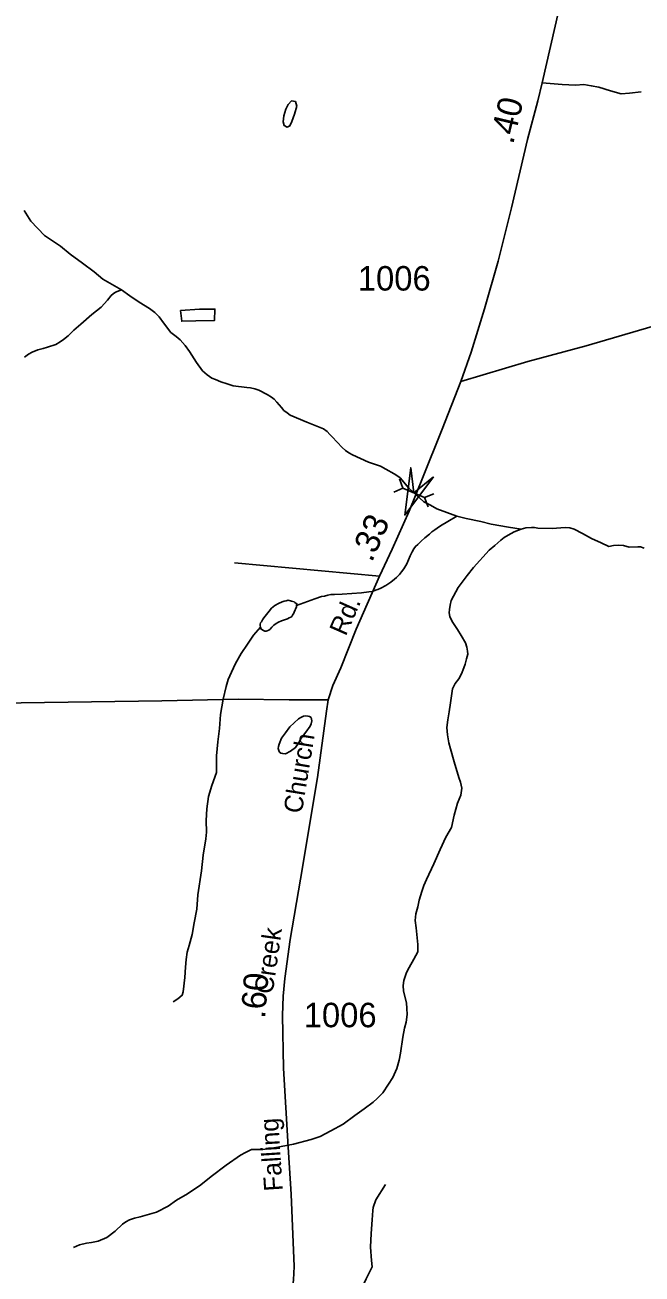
# Model space of a CAD drawing. Extents: x 2206922 to 2357709, y 510027 to 673830.
# Drawn here: x 2248244 to 2251391, y 564362 to 570736 of the extents above; entities that cross this region are included whole.
import ezdxf

# ---------------------------------------------------------------- set-up
doc = ezdxf.new("R2010")
doc.units = 0
for name, color, linetype in [('Exist Hydrographic Creek Single Shore', 7, 'Continuous'), ('Exist Hydrographic Misc Water Feature', 7, 'Continuous'), ('Exist Road Non-System Type 51', 7, 'Continuous'), ('Exist Road Secondary Mileage Hundredths English Label', 7, 'Continuous'), ('Exist Road Secondary Structure Pipe Attributed CELL', 7, 'Continuous'), ('Exist Road Secondary Structure Pipe CELL', 7, 'Continuous'), ('Exist Road Secondary Type 51 Attributed', 7, 'Continuous'), ('Exist Road Secondary Type 51 Label', 7, 'Continuous'), ('Exist Road Secondary Type 51 Number Label', 7, 'Continuous')]:
    doc.layers.add(name, color=color, linetype=linetype)

msp = doc.modelspace()

# ---------------------------------------------------------------- linework, layer by layer
at = {"layer": 'Exist Hydrographic Creek Single Shore'}
for points in [[(2248239, 569789.7), (2248273.1, 569734.3), (2248343.8, 569660.8), (2248424.6, 569607.3), (2248474.6, 569565.6), (2248536.8, 569520.2), (2248597, 569477), (2248641.3, 569439.1), (2248735.9, 569383.9)], [(2248240.9, 569040), (2248261, 569056.1), (2248280.4, 569066.5), (2248308.5, 569078.5), (2248336.6, 569084.8), (2248358.6, 569091.2), (2248400.6, 569105.6), (2248424, 569119.5), (2248440.2, 569131.6), (2248463.6, 569150), (2248493.7, 569178.3), (2248529.4, 569208.6), (2248584.9, 569259), (2248632.7, 569295.2), (2248664.3, 569331.5), (2248684, 569355.6), (2248693.8, 569363.9), (2248706.1, 569371.8), (2248735.9, 569383.9)], [(2248735.9, 569383.9), (2248778.1, 569354.4), (2248826.1, 569320.8), (2248878.6, 569289.4), (2248906.9, 569269.3), (2248928.8, 569245.7), (2248951, 569216), (2248987.9, 569166.2), (2249015.6, 569146.3), (2249035.9, 569128.6), (2249060.3, 569100.6), (2249082.6, 569068.8), (2249118.7, 569013.5), (2249149.3, 568971.6), (2249173.2, 568949.8), (2249197.4, 568933.9), (2249215.3, 568926.4), (2249243.4, 568914.4), (2249275.4, 568904.8), (2249305.7, 568894.9), (2249375.4, 568885.6), (2249393.9, 568883.6), (2249415.8, 568879.9), (2249437.3, 568872.2), (2249479.8, 568850.4), (2249501.9, 568836.5), (2249514, 568826.6), (2249528.4, 568810.6), (2249552.2, 568783.1), (2249564.7, 568769.1), (2249580.7, 568757.3), (2249596.5, 568745.2), (2249681, 568708.2), (2249748.8, 568682.5), (2249767.1, 568674.9), (2249785.1, 568660.8), (2249799.5, 568646.9), (2249811.2, 568633.4), (2249861.8, 568579.5), (2249878.2, 568563.6), (2249895.8, 568552.1), (2249914.1, 568542), (2249996.3, 568504.9), (2250056.4, 568485.3), (2250084.9, 568469.6), (2250126.9, 568445.8), (2250144.8, 568433.8), (2250157.3, 568424.2), (2250201.4, 568372.6), (2250277.9, 568303.1), (2250312.3, 568285.3), (2250344.1, 568267.5), (2250446.4, 568228.5)], [(2250446.4, 568228.5), (2250494.6, 568216.9), (2250568.6, 568201.6), (2250622.3, 568187.8), (2250710.9, 568172.9), (2250774.7, 568163.2)], [(2250774.7, 568163.2), (2250798.7, 568169.4), (2250826.8, 568171.6), (2250842.4, 568171.7), (2250860.4, 568167.7), (2250932.6, 568166.6), (2250998.8, 568170.8), (2251022.6, 568169.2), (2251044.8, 568163.5), (2251087, 568141.7), (2251133.3, 568116.1), (2251183.4, 568092.7), (2251221.1, 568074.9), (2251245.3, 568078.9), (2251271.1, 568081.5), (2251297.2, 568079.6), (2251325.7, 568071.7), (2251369.1, 568072), (2251383.1, 568072.3), (2251401.3, 568066.3)]]:
    msp.add_lwpolyline(points, dxfattribs=at)
at = {"layer": 'Exist Hydrographic Misc Water Feature'}
for points in [[(2249603.9, 570348.7), (2249623.5, 570344.6), (2249629.7, 570320.9), (2249618.4, 570280.9), (2249604.5, 570242.8), (2249594.8, 570220.7), (2249580.5, 570214.4), (2249566.5, 570222.2), (2249560.6, 570242.2), (2249564.3, 570272.4), (2249573.7, 570306.2), (2249585.8, 570330.4), (2249603.9, 570348.7)], [(2249036.7, 569278.5), (2249134.7, 569285.2), (2249212.6, 569286), (2249210.6, 569228), (2249115.4, 569225.3), (2249043, 569224.4), (2249036.7, 569278.5)], [(2249628.7, 567774), (2249722.6, 567806.9), (2249756.4, 567819.2), (2249772, 567821.3), (2249788, 567825.4), (2249804, 567829.5), (2249821.8, 567829.6), (2249861.8, 567832.1), (2249959.8, 567838.8), (2249998, 567843.2), (2250015.8, 567845.4), (2250031.8, 567851.5), (2250043.9, 567855.3), (2250059.7, 567861.5), (2250083.7, 567875.7), (2250109.5, 567892.1), (2250129.2, 567908.2), (2250139, 567916), (2250154.8, 567932.3), (2250164.9, 567944.5), (2250177, 567960.6), (2250190.7, 567986.5), (2250207.9, 568026.9), (2250218.2, 568046.9), (2250228, 568062.8), (2250236, 568075), (2250247.9, 568085), (2250265.3, 568100.9), (2250283.4, 568119.4), (2250307.6, 568137.6), (2250318.9, 568149.6), (2250335.1, 568159.8), (2250347, 568167.7), (2250363.2, 568179.9), (2250400.9, 568202.2), (2250446.4, 568228.5)], [(2250417.7, 567798.5), (2250453.4, 567865), (2250499.1, 567927), (2250530.9, 567967.3), (2250611.9, 568056), (2250639.8, 568080.2), (2250671.4, 568106.2), (2250687.3, 568120.5), (2250708.9, 568132.6), (2250738.8, 568148.8), (2250774.7, 568163.2)], [(2248491.6, 564496.5), (2248521.6, 564510.6), (2248557.9, 564518.9), (2248583.7, 564523.2), (2248617.3, 564529.5), (2248661.2, 564548), (2248703.3, 564580.2), (2248740.8, 564616.3), (2248758.4, 564628.6), (2248776.7, 564638.9), (2248802.3, 564647.2), (2248830.6, 564653), (2248914.1, 564677.7), (2248974.1, 564708.4), (2249015.8, 564738.7), (2249073.4, 564770.9), (2249141, 564817.5), (2249192.7, 564859.9), (2249270.2, 564916.8), (2249343.4, 564969), (2249369.3, 564981.3), (2249399.2, 564997.5), (2249457.6, 564998), (2249515.1, 565006.4), (2249613.1, 565025.3), (2249703.1, 565048.2), (2249748.6, 565064.4), (2249804.4, 565092.9), (2249866.3, 565127.4), (2249925.6, 565170), (2249973.4, 565204.1), (2250019.1, 565238.6), (2250040.8, 565256.8), (2250068.9, 565287.1), (2250098.2, 565331.3), (2250120.2, 565365.3), (2250139.7, 565411.4), (2250153.2, 565453.6), (2250159.1, 565489.6), (2250170.4, 565569.8), (2250179.6, 565615.9), (2250187.6, 565647.6), (2250193.4, 565685.6), (2250191.1, 565717.5), (2250189.1, 565745.8), (2250174.3, 565805.6), (2250172.3, 565833.5), (2250175.9, 565859.3), (2250189.7, 565899.9), (2250203.2, 565925.8), (2250226.8, 565968), (2250246.9, 566006), (2250248.3, 566043.9), (2250244.2, 566077.8), (2250239.9, 566127.9), (2250233.4, 566165.8), (2250237.1, 566199.7), (2250246.9, 566235.9), (2250254.7, 566270), (2250268.4, 566314.2), (2250278.1, 566344), (2250291.6, 566374.4), (2250329.1, 566454.3), (2250362.3, 566528.7), (2250389.6, 566591.1), (2250419.3, 566641), (2250433.1, 566703), (2250450.1, 566765.3), (2250466.1, 566805.4), (2250471.8, 566841.5), (2250465.7, 566871.2), (2250457.3, 566895.2), (2250432.9, 566975.1), (2250414.4, 567042.8), (2250405.8, 567072.9), (2250399.7, 567112.8), (2250395.4, 567150.7), (2250400.7, 567190.8), (2250406.6, 567230.9), (2250414.2, 567276.8), (2250423.6, 567348.8), (2250437.4, 567375.1), (2250457.1, 567398.9), (2250470.8, 567425.2), (2250482.7, 567455.4), (2250488.7, 567473.2), (2250496.6, 567501.2), (2250502.4, 567525.5), (2250500.3, 567541.2), (2250497.7, 567561.5), (2250489.9, 567583.3), (2250469.4, 567620.9), (2250449.3, 567650.7), (2250426.7, 567686.5), (2250417.1, 567702.6), (2250410.9, 567716.5), (2250406.6, 567736.6), (2250408.5, 567752.5), (2250412, 567774.3), (2250417.7, 567798.5)], [(2249445.6, 567662.5), (2249443.5, 567670.5), (2249443.1, 567678.7), (2249445.3, 567684.4), (2249449.4, 567690.7), (2249455.4, 567700.8), (2249461.3, 567710.8), (2249488.6, 567744.8), (2249500.7, 567759.2), (2249518.3, 567773.2), (2249536.6, 567783.4), (2249556.3, 567791.4), (2249566.3, 567795.6), (2249576.4, 567797.7), (2249586.6, 567799.8), (2249602.4, 567795.8), (2249616.4, 567792.1), (2249620.3, 567788.2), (2249626.4, 567784), (2249630.9, 567782.2), (2249628.7, 567774)], [(2249628.7, 567774), (2249628.7, 567766.3), (2249617, 567740.1), (2249614.7, 567733.9), (2249608.8, 567723.9), (2249605.3, 567717.9), (2249599.1, 567714), (2249591.1, 567709.9), (2249583.3, 567705.8), (2249551.4, 567695.6), (2249537.2, 567687.6), (2249525.1, 567681.3), (2249513.2, 567673.4), (2249503.4, 567663.1), (2249493.7, 567652.8), (2249487.6, 567646.9), (2249479.6, 567644.8), (2249473.6, 567642.9), (2249467.9, 567642.9), (2249459.7, 567645), (2249451.7, 567650.7), (2249447.8, 567652.4), (2249445.6, 567662.5)], [(2248999.2, 565750.1), (2249023.6, 565766.3), (2249045.3, 565784.5), (2249050.8, 565802.3), (2249058.6, 565874.5), (2249062.1, 565928.4), (2249065.4, 565966.4), (2249071.3, 566004.4), (2249081.2, 566038.6), (2249096.6, 566094.7), (2249106, 566154.5), (2249119.5, 566224.6), (2249125.1, 566296.8), (2249144.1, 566418.8), (2249153.1, 566499), (2249166.7, 566582.9), (2249170.4, 566616.8), (2249167.9, 566676.8), (2249171.2, 566735.1), (2249180.6, 566799), (2249196.4, 566855), (2249219.8, 566921.2), (2249221.2, 567006.9), (2249228.2, 567077.3), (2249235.8, 567145.1), (2249241.3, 567217.2), (2249254.6, 567295.1), (2249270, 567359.3), (2249279.9, 567395.5), (2249297.7, 567433.8), (2249317, 567477.9), (2249346.7, 567527.8), (2249378.5, 567576.1), (2249410.1, 567622.5), (2249445.6, 567662.5)], [(2249534.5, 567043.6), (2249536.2, 567053.5), (2249540.5, 567065.9), (2249552.2, 567095.7), (2249571.9, 567124), (2249595.4, 567154.1), (2249639.3, 567194.5), (2249651.2, 567202.5), (2249665, 567208.5), (2249675, 567210.6), (2249687.1, 567208.8), (2249695.3, 567206.8), (2249703.3, 567201.1), (2249705.4, 567193.1), (2249707.4, 567185.1), (2249703.5, 567169), (2249697.6, 567156.9), (2249676, 567127), (2249651.8, 567096.6), (2249638.1, 567070.6), (2249624.2, 567048.4), (2249598.7, 567030.3), (2249572.9, 567016), (2249558.9, 567018.1), (2249548.9, 567020), (2249542.7, 567025.8), (2249538.4, 567033.7), (2249534.5, 567043.6)]]:
    msp.add_lwpolyline(points, dxfattribs=at)
at = {"layer": 'Exist Road Non-System Type 51'}
msp.add_line((2249311.8, 567991.6), (2250052.2, 567922.8), dxfattribs=at)
for points in [[(2250882.3, 570441.3), (2250983.5, 570431.8), (2251052.3, 570428), (2251094.4, 570431.8), (2251132.6, 570426), (2251170.8, 570418.4), (2251230, 570399.3), (2251285.4, 570384), (2251327.5, 570387.8), (2251386.7, 570395.5)], [(2249892.5, 564126), (2249937.6, 564242.2), (2249984.7, 564336.6), (2250004.4, 564378.8), (2250014.4, 564398.8), (2250012, 564430.8), (2250005.4, 564498.8), (2250009, 564568.7), (2250014.4, 564638.7), (2250018, 564686.6), (2250019.9, 564700.6), (2250033.5, 564740.7), (2250082.9, 564819.1)]]:
    msp.add_lwpolyline(points, dxfattribs=at)
at = {"layer": 'Exist Road Secondary Structure Pipe Attributed CELL'}
msp.add_lwpolyline([(2250328.1, 568429.3), (2250180.9, 568234.8), (2250211.1, 568476.8), (2250226.8, 568347.8)], close=True, dxfattribs=at)
at = {"layer": 'Exist Road Secondary Structure Pipe CELL'}
for p, q in [((2250124.6, 568351.7), (2250171.3, 568371.7)), ((2250153.9, 568419.4), (2250171.3, 568371.7)), ((2250171.3, 568371.7), (2250282.3, 568323.8)), ((2250329, 568343.8), (2250282.3, 568323.8)), ((2250299.8, 568276.1), (2250282.3, 568323.8))]:
    msp.add_line(p, q, dxfattribs=at)
at = {"layer": 'Exist Road Secondary Type 51 Attributed'}
for points in [[(2250467.3, 568916.3), (2250807.9, 569018.6), (2251107.1, 569099.2), (2251947.2, 569344.9), (2252586.5, 569525.3), (2254037, 569910.6), (2254393.3, 570013.3), (2255973.3, 570449.6), (2256015.6, 570461.3), (2256185.7, 570506.2), (2256293.2, 570536.3), (2256317.3, 570543.1), (2256670.2, 570659.9), (2256770.5, 570695.3), (2257212.7, 570851.4), (2257512.8, 570973.4), (2257660.4, 571023.2), (2257764.7, 571065), (2257830.5, 571095.5), (2257891.8, 571133.7), (2257974.9, 571207.9), (2258147.6, 571395.6), (2258215.6, 571472.8)], [(2250467.3, 568916.3), (2250520.2, 569066.6), (2250587.9, 569287.3), (2250657, 569531), (2250726, 569802.3), (2250807.8, 570150.8), (2250859.4, 570349.6), (2250882.3, 570441.3), (2250966.4, 570812.2), (2251014.1, 570980.4)], [(2249790.1, 567292.7), (2249814.3, 567364.4), (2249854, 567455.2), (2249933.3, 567652.3), (2250052.2, 567922.8), (2250116.1, 568061), (2250203.1, 568255.5), (2250272.1, 568423.7), (2250371.3, 568673.7), (2250467.3, 568916.3)], [(2243785.4, 567002.3), (2243988.2, 566946.5), (2244130.5, 566913.6), (2244241.9, 566894.2), (2244322.7, 566893.4), (2244396.5, 566895.9), (2244468.4, 566904.4), (2244560.2, 566925.1), (2244675.9, 566968.2), (2244817.3, 567031.3), (2244930.8, 567088.2), (2244990.5, 567112.6), (2245056.3, 567131.3), (2245112.7, 567144.3), (2245230.3, 567158.4), (2246139.4, 567206.4), (2246790.3, 567242.2), (2247700.7, 567256.9), (2248223.7, 567277.4), (2248583, 567281.2), (2248941, 567286.3), (2249330.9, 567296), (2249591.9, 567292.7), (2249790.1, 567292.7)], [(2249576.5, 564151.3), (2249592, 564197.4), (2249604.6, 564260.6), (2249613.6, 564332.3), (2249616.1, 564400.1), (2249600.8, 564769.8), (2249586.7, 565008.4), (2249562.4, 565412.7), (2249558, 565680.4), (2249561.2, 565780.4), (2249568.4, 565870.4), (2249596.8, 566068.5), (2249648.3, 566376.8), (2249736.1, 566895.3), (2249782.4, 567233.9), (2249790.1, 567292.7)]]:
    msp.add_lwpolyline(points, dxfattribs=at)

# ---------------------------------------------------------------- texts
at = {"layer": 'Exist Road Secondary Mileage Hundredths English Label'}
for s, rotation, p in [('.40', 76.61926, (2250733.4, 570123.2)), ('.33', 66.13561, (2250012.6, 567989.8)), ('.60', 85.42517, (2249468.2, 565662.6))]:
    msp.add_text(s, height=125, rotation=rotation, dxfattribs=at).set_placement(p)
at = {"layer": 'Exist Road Secondary Type 51 Label'}
for s, rotation, p in [('Rd.', 66.13561, (2249879.5, 567613.4)), ('Church', 80.68453, (2249655.5, 566708.1)), ('Creek', 81.84187, (2249506.7, 565786.8)), ('Falling', 93.6553, (2249559, 564787.4))]:
    msp.add_text(s, height=95, rotation=rotation, dxfattribs=at).set_placement(p)
at = {"layer": 'Exist Road Secondary Type 51 Number Label'}
for p in [(2249941.3, 569380.6), (2249665.5, 565621.1)]:
    msp.add_text('1006', height=125, dxfattribs=at).set_placement(p)

doc.saveas('drawing.dxf')
